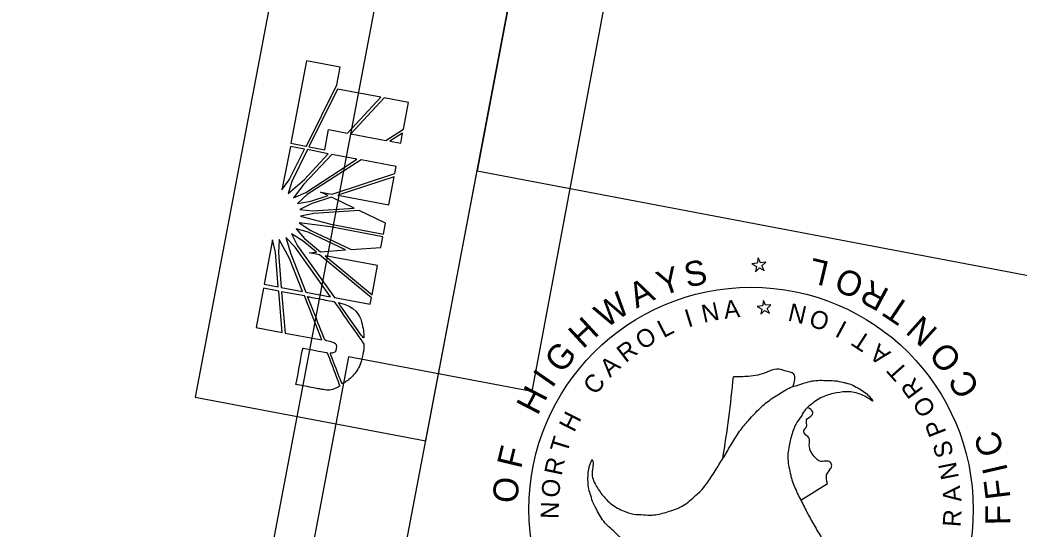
# Model space of a CAD drawing. Extents: x 1615680 to 1617075, y 898420 to 901376.
# Drawn here: x 1616769.3 to 1616971.6, y 900660.3 to 900763.4 of the extents above; entities that cross this region are included whole.
import ezdxf

# ---------------------------------------------------------------- set-up
doc = ezdxf.new("R2010")
doc.units = 0
for name, color, linetype in [('Default', 7, 'Continuous'), ('DEV BORDER CELL', 7, 'Continuous'), ('DEV DOT SWIRL SEAL CELL', 7, 'Continuous'), ('Scratch_Level_0', 7, 'Continuous'), ('Sheet Clip Boundary CELL', 7, 'Continuous'), ('Sheet Plan CELL', 7, 'Continuous'), ('Text', 7, 'Continuous')]:
    doc.layers.add(name, color=color, linetype=linetype)

msp = doc.modelspace()

# ---------------------------------------------------------------- linework, layer by layer
at = {"layer": 'Default'}
for p, q in [((1616827.31, 900755.17), (1616824.15, 900738.45)), ((1616834.16, 900753.88), (1616827.31, 900755.17)), ((1616833.49, 900750.32), (1616834.16, 900753.88)), ((1616827.31, 900737.85), (1616833.49, 900750.32)), ((1616833.63, 900749.42), (1616827.78, 900737.76)), ((1616842.41, 900747.76), (1616833.63, 900749.42)), ((1616835.63, 900740.51), (1616842.41, 900747.76)), ((1616843.03, 900747.65), (1616836.29, 900740.38)), ((1616847.97, 900746.71), (1616843.03, 900747.65)), ((1616846.95, 900741.32), (1616847.97, 900746.71)), ((1616831.04, 900737.15), (1616831.81, 900741.23)), ((1616831.81, 900741.23), (1616835.63, 900740.51)), ((1616836.29, 900740.38), (1616843.4, 900739.04)), ((1616843.4, 900739.04), (1616846.95, 900741.32)), ((1616846.8, 900740.53), (1616844.18, 900738.89)), ((1616846.41, 900738.47), (1616846.8, 900740.53)), ((1616824.07, 900737.82), (1616822.36, 900729.01)), ((1616826.93, 900737.28), (1616824.07, 900737.82)), ((1616824.15, 900738.45), (1616827.22, 900737.87)), ((1616827.22, 900737.87), (1616827.31, 900737.85)), ((1616827.78, 900737.76), (1616827.84, 900737.75)), ((1616827.84, 900737.75), (1616831.04, 900737.15)), ((1616844.18, 900738.89), (1616846.41, 900738.47)), ((1616823.84, 900731.04), (1616826.93, 900737.28)), ((1616827.54, 900737.17), (1616824.37, 900730.71)), ((1616832.45, 900736.19), (1616826.81, 900730.17)), ((1616826.95, 900731.13), (1616831.74, 900736.32)), ((1616831.74, 900736.32), (1616827.54, 900737.17)), ((1616837.54, 900735.22), (1616832.45, 900736.19)), ((1616827.18, 900728.51), (1616837.54, 900735.22)), ((1616838.37, 900735.07), (1616827.5, 900728.08)), ((1616845.51, 900733.72), (1616838.37, 900735.07)), ((1616845.25, 900732.31), (1616845.51, 900733.72)), ((1616832.52, 900728.14), (1616845.25, 900732.31)), ((1616845.08, 900731.66), (1616833.66, 900727.92)), ((1616844.01, 900725.97), (1616845.08, 900731.66)), ((1616822.36, 900729.01), (1616823.84, 900731.04)), ((1616823.59, 900728.31), (1616826.95, 900731.13)), ((1616824.37, 900730.71), (1616823.59, 900728.31)), ((1616826.81, 900730.17), (1616824.69, 900727.39)), ((1616824.69, 900727.39), (1616827.18, 900728.51)), ((1616827.5, 900728.08), (1616825.48, 900726.27)), ((1616828.21, 900726.76), (1616831.69, 900727.87)), ((1616832.4, 900727.52), (1616828.28, 900726.16)), ((1616831.69, 900727.87), (1616830.19, 900728.58)), ((1616830.19, 900728.58), (1616832.52, 900728.14)), ((1616836.99, 900725.33), (1616832.4, 900727.52)), ((1616833.66, 900727.92), (1616844.01, 900725.97)), ((1616825.48, 900726.27), (1616828.21, 900726.76)), ((1616828.28, 900726.16), (1616825.97, 900725.01)), ((1616828.57, 900724.79), (1616836.99, 900725.33)), ((1616825.97, 900725.01), (1616828.57, 900724.79)), ((1616828.83, 900724.24), (1616826.09, 900723.67)), ((1616826.09, 900723.67), (1616832.28, 900722.08)), ((1616837.99, 900724.87), (1616828.83, 900724.24)), ((1616843.31, 900722.28), (1616837.99, 900724.87)), ((1616832.18, 900721.51), (1616825.84, 900722.36)), ((1616825.84, 900722.36), (1616828.18, 900720.79)), ((1616842.79, 900719.51), (1616832.18, 900721.51)), ((1616832.28, 900722.08), (1616842.89, 900720.07)), ((1616842.89, 900720.07), (1616843.31, 900722.28)), ((1616825.04, 900717.42), (1616823.18, 900719.36)), ((1616823.18, 900719.36), (1616824.14, 900716.04)), ((1616824.31, 900720.1), (1616825.54, 900717.68)), ((1616826.67, 900718.65), (1616824.31, 900720.1)), ((1616825.24, 900721.11), (1616826.96, 900719.15)), ((1616827.65, 900720.42), (1616825.24, 900721.11)), ((1616826.96, 900719.15), (1616830.18, 900716.49)), ((1616835.2, 900716.86), (1616827.65, 900720.42)), ((1616828.18, 900720.79), (1616836.35, 900716.92)), ((1616842.37, 900717.33), (1616842.79, 900719.51)), ((1616820.45, 900718.87), (1616818.76, 900709.92)), ((1616821.03, 900716.4), (1616820.45, 900718.87)), ((1616821.82, 900718.94), (1616821.64, 900716.28)), ((1616823.88, 900715.14), (1616821.82, 900718.94)), ((1616832.19, 900707.38), (1616825.04, 900717.42)), ((1616825.54, 900717.68), (1616833.03, 900707.22)), ((1616829.39, 900716.41), (1616826.67, 900718.65)), ((1616836.35, 900716.92), (1616842.37, 900717.33)), ((1616821.61, 900709.38), (1616821.03, 900716.4)), ((1616821.64, 900716.28), (1616822.22, 900709.27)), ((1616826.53, 900708.45), (1616823.88, 900715.14)), ((1616824.14, 900716.04), (1616827.22, 900708.32)), ((1616827.87, 900716.29), (1616829.39, 900716.41)), ((1616829.97, 900715.89), (1616827.87, 900716.29)), ((1616840.5, 900707.17), (1616829.97, 900715.89)), ((1616830.18, 900716.49), (1616835.2, 900716.86)), ((1616841.73, 900713.72), (1616831.12, 900715.68)), ((1616831.12, 900715.68), (1616840.61, 900707.79)), ((1616840.61, 900707.79), (1616841.73, 900713.72)), ((1616818.64, 900709.09), (1616817.14, 900701.13)), ((1616821.71, 900708.51), (1616818.64, 900709.09)), ((1616818.76, 900709.92), (1616821.61, 900709.38)), ((1616822.22, 900709.27), (1616826.53, 900708.45)), ((1616822.41, 900700.13), (1616821.71, 900708.51)), ((1616826.9, 900707.53), (1616822.29, 900708.4)), ((1616822.29, 900708.4), (1616823.02, 900700.02)), ((1616830.44, 900698.62), (1616826.9, 900707.53)), ((1616827.22, 900708.32), (1616832.19, 900707.38)), ((1616833.03, 900707.22), (1616840.25, 900705.86)), ((1616840.25, 900705.86), (1616840.5, 900707.17)), ((1616817.14, 900701.13), (1616822.41, 900700.13)), ((1616823.02, 900700.02), (1616830.44, 900698.62))]:
    msp.add_line(p, q, dxfattribs=at)
for points in [[(1616827.78, 900737.76), (1616827.84, 900737.75), (1616831.04, 900737.15), (1616831.81, 900741.23), (1616835.63, 900740.51), (1616842.41, 900747.76), (1616833.63, 900749.42), (1616827.78, 900737.76)], [(1616836.29, 900740.38), (1616843.4, 900739.04), (1616846.95, 900741.32), (1616847.97, 900746.71), (1616843.03, 900747.65), (1616836.29, 900740.38), (1616836.29, 900740.38)], [(1616846.41, 900738.47), (1616846.41, 900738.47), (1616846.8, 900740.53), (1616844.18, 900738.89), (1616846.41, 900738.47)], [(1616823.84, 900731.04), (1616826.93, 900737.28), (1616824.07, 900737.82), (1616822.36, 900729.01), (1616823.84, 900731.04)], [(1616823.59, 900728.31), (1616826.95, 900731.13), (1616831.74, 900736.32), (1616827.54, 900737.17), (1616824.37, 900730.71), (1616823.59, 900728.31)], [(1616824.69, 900727.39), (1616827.18, 900728.51), (1616837.54, 900735.22), (1616832.45, 900736.19), (1616826.81, 900730.17), (1616824.69, 900727.39)], [(1616825.48, 900726.27), (1616828.21, 900726.76), (1616831.69, 900727.87), (1616830.19, 900728.58), (1616832.52, 900728.14), (1616845.25, 900732.31), (1616845.51, 900733.72), (1616838.37, 900735.07), (1616827.5, 900728.08), (1616825.48, 900726.27)], [(1616844.01, 900725.97), (1616845.08, 900731.66), (1616833.66, 900727.92), (1616844.01, 900725.97)], [(1616825.97, 900725.01), (1616828.57, 900724.79), (1616836.99, 900725.33), (1616832.4, 900727.52), (1616828.28, 900726.16), (1616825.97, 900725.01)], [(1616826.09, 900723.67), (1616832.28, 900722.08), (1616842.89, 900720.07), (1616843.31, 900722.28), (1616837.99, 900724.87), (1616828.83, 900724.24), (1616826.09, 900723.67)], [(1616828.18, 900720.79), (1616836.35, 900716.92), (1616842.37, 900717.33), (1616842.79, 900719.51), (1616832.18, 900721.51), (1616825.84, 900722.36), (1616828.18, 900720.79)], [(1616827.22, 900708.32), (1616832.19, 900707.38), (1616825.04, 900717.42), (1616823.18, 900719.36), (1616824.14, 900716.04), (1616827.22, 900708.32)], [(1616824.31, 900720.1), (1616825.54, 900717.68), (1616833.03, 900707.22), (1616840.25, 900705.86), (1616840.5, 900707.17), (1616829.97, 900715.89), (1616827.87, 900716.29), (1616829.39, 900716.41), (1616826.67, 900718.65), (1616824.31, 900720.1)], [(1616825.24, 900721.11), (1616826.96, 900719.15), (1616830.18, 900716.49), (1616835.2, 900716.86), (1616827.65, 900720.42), (1616825.24, 900721.11)], [(1616821.03, 900716.4), (1616820.45, 900718.87), (1616818.76, 900709.92), (1616821.61, 900709.38), (1616821.03, 900716.4)], [(1616822.22, 900709.27), (1616826.53, 900708.45), (1616823.88, 900715.14), (1616821.82, 900718.94), (1616821.64, 900716.28), (1616822.22, 900709.27)], [(1616840.61, 900707.79), (1616841.73, 900713.72), (1616831.12, 900715.68), (1616840.61, 900707.79)], [(1616822.41, 900700.13), (1616821.71, 900708.51), (1616818.64, 900709.09), (1616817.14, 900701.13), (1616822.41, 900700.13)], [(1616830.44, 900698.62), (1616826.9, 900707.53), (1616822.29, 900708.4), (1616823.02, 900700.02), (1616830.44, 900698.62)]]:
    msp.add_lwpolyline(points, dxfattribs=at)
for points in [[(1616833.44, 900696.87), (1616833.35, 900696.4), (1616833.01, 900696.04), (1616832.1, 900696.03), (1616832.1, 900696.03), (1616834.55, 900689.66), (1616834.55, 900689.66), (1616836.73, 900691.07), (1616838.37, 900693.67), (1616838.81, 900696.04), (1616838.93, 900696.66), (1616838.97, 900697.14), (1616838.96, 900697.82), (1616838.96, 900697.82), (1616832.91, 900706.39), (1616832.91, 900706.39), (1616832.91, 900706.39), (1616827.55, 900707.4), (1616827.55, 900707.4), (1616827.55, 900707.4), (1616831.11, 900698.49), (1616831.11, 900698.49), (1616833.11, 900698.11), (1616833.56, 900697.52), (1616833.44, 900696.87)], [(1616833.44, 900696.87), (1616833.35, 900696.4), (1616833.01, 900696.04), (1616832.1, 900696.03), (1616832.1, 900696.03), (1616834.55, 900689.66), (1616834.55, 900689.66), (1616836.73, 900691.07), (1616838.37, 900693.67), (1616838.81, 900696.04), (1616838.93, 900696.66), (1616838.97, 900697.14), (1616838.96, 900697.82), (1616838.96, 900697.82), (1616832.91, 900706.39), (1616832.91, 900706.39), (1616832.91, 900706.39), (1616827.55, 900707.4), (1616827.55, 900707.4), (1616827.55, 900707.4), (1616831.11, 900698.49), (1616831.11, 900698.49), (1616833.11, 900698.11), (1616833.56, 900697.52), (1616833.44, 900696.87)], [(1616833.75, 900706.23), (1616833.75, 900706.23), (1616838.97, 900698.83), (1616838.97, 900698.83), (1616838.8, 900702), (1616837.36, 900705.4), (1616833.75, 900706.23)], [(1616833.75, 900706.23), (1616833.75, 900706.23), (1616838.97, 900698.83), (1616838.97, 900698.83), (1616838.8, 900702), (1616837.36, 900705.4), (1616833.75, 900706.23)], [(1616826.59, 900696.98), (1616826.59, 900696.98), (1616825.2, 900689.61), (1616825.2, 900689.61), (1616825.2, 900689.61), (1616829.81, 900688.74), (1616829.81, 900688.74), (1616829.81, 900688.74), (1616830.29, 900688.65), (1616830.29, 900688.65), (1616831.74, 900688.38), (1616832.97, 900688.64), (1616834.09, 900689.29), (1616834.09, 900689.29), (1616831.55, 900696.04), (1616831.46, 900696.06), (1616831.46, 900696.06), (1616826.59, 900696.98), (1616826.59, 900696.98)], [(1616826.59, 900696.98), (1616826.59, 900696.98), (1616825.2, 900689.61), (1616825.2, 900689.61), (1616825.2, 900689.61), (1616829.81, 900688.74), (1616829.81, 900688.74), (1616829.81, 900688.74), (1616830.29, 900688.65), (1616830.29, 900688.65), (1616831.74, 900688.38), (1616832.97, 900688.64), (1616834.09, 900689.29), (1616834.09, 900689.29), (1616831.55, 900696.04), (1616831.46, 900696.06), (1616831.46, 900696.06), (1616826.59, 900696.98), (1616826.59, 900696.98)]]:
    msp.add_open_spline(points, degree=3, dxfattribs=at)
at = {"layer": 'DEV BORDER CELL'}
for points in [[(1616905.88, 900964.73), (1616861.86, 900732.87), (1616996.95, 900707.23), (1617040.97, 900939.08)], [(1616840.59, 900620.87), (1616861.86, 900732.87), (1616996.95, 900707.23), (1616975.68, 900595.22)]]:
    msp.add_lwpolyline(points, close=True, dxfattribs=at)
at = {"layer": 'DEV DOT SWIRL SEAL CELL'}
for p, q in [((1616918.77, 900715.25), (1616918.56, 900714.19)), ((1616919.23, 900714.26), (1616918.77, 900715.25)), ((1616918.56, 900714.19), (1616917.51, 900714.02)), ((1616917.51, 900714.02), (1616918.44, 900713.51)), ((1616918.44, 900713.51), (1616918.23, 900712.45)), ((1616918.23, 900712.45), (1616919.03, 900713.2)), ((1616919.03, 900713.2), (1616920, 900712.69)), ((1616920.32, 900714.39), (1616919.23, 900714.26)), ((1616919.52, 900713.63), (1616920.32, 900714.39)), ((1616920, 900712.69), (1616919.52, 900713.63)), ((1616919.62, 900705.56), (1616918.56, 900705.39)), ((1616918.56, 900705.39), (1616919.49, 900704.89)), ((1616919.82, 900706.62), (1616919.62, 900705.56)), ((1616920.28, 900705.64), (1616919.82, 900706.62)), ((1616921.37, 900705.76), (1616920.28, 900705.64)), ((1616920.58, 900705.01), (1616921.37, 900705.76)), ((1616921.05, 900704.06), (1616920.58, 900705.01)), ((1616919.49, 900704.89), (1616919.29, 900703.83)), ((1616919.29, 900703.83), (1616920.08, 900704.57)), ((1616920.08, 900704.57), (1616921.05, 900704.06)), ((1616927.43, 900666.17), (1616932.82, 900669.53))]:
    msp.add_line(p, q, dxfattribs=at)
msp.add_arc((1616681.63, 900713.24), 233.19, 350.4529, 354.5729, dxfattribs=at)
for points in [[(1616925.85, 900689.2), (1616926.01, 900691.68), (1616924.16, 900692.4), (1616922.56, 900692.74), (1616920.51, 900692.09), (1616916.81, 900691.24), (1616913.77, 900691.18)], [(1616885.09, 900674.44), (1616885.15, 900674.35), (1616885.14, 900671.73), (1616885.9, 900669.21), (1616887.35, 900667.1), (1616889.36, 900665.16), (1616892, 900663.79), (1616894.06, 900663.26), (1616895.09, 900663.25), (1616896.88, 900663.16), (1616898.33, 900663.29), (1616901.12, 900664.05), (1616903.92, 900665.29), (1616906.42, 900667.39), (1616906.62, 900667.57), (1616908.56, 900669.82), (1616910.25, 900672.43), (1616911.82, 900674.91), (1616913.38, 900677.54), (1616915.02, 900680.12), (1616916.87, 900682.4), (1616919.19, 900684.83), (1616921.43, 900686.67), (1616924.06, 900688.3), (1616925.37, 900689.03), (1616926.65, 900689.42), (1616929.69, 900690.32), (1616932.83, 900690.43), (1616934.72, 900690.32), (1616936.29, 900689.97), (1616936.55, 900689.92), (1616939.3, 900688.71), (1616941.48, 900686.96), (1616942.02, 900686.2)], [(1616942.02, 900686.2), (1616939.76, 900687.51), (1616937.22, 900688.12), (1616934.64, 900687.9), (1616931.95, 900687.13), (1616929.47, 900685.55), (1616927.98, 900684.03), (1616927.45, 900683.12), (1616926.46, 900681.67), (1616925.87, 900680.28), (1616925.1, 900677.53), (1616924.79, 900674.45), (1616925.36, 900671.25), (1616925.42, 900670.99), (1616926.44, 900668.18), (1616927.8, 900665.43), (1616929.16, 900662.79), (1616930.68, 900660.13), (1616932.13, 900657.42), (1616933.14, 900654.69), (1616934.09, 900651.45), (1616934.55, 900648.6), (1616934.65, 900645.52), (1616934.64, 900643.99), (1616934.34, 900642.71), (1616933.59, 900639.66), (1616932.13, 900636.85), (1616931.1, 900635.29), (1616929.97, 900634.12), (1616929.8, 900633.9), (1616927.41, 900632.12), (1616924.81, 900631.11), (1616923.83, 900630.99)], [(1616932.82, 900669.53), (1616932.64, 900671.29), (1616933.43, 900672.58), (1616933.66, 900673.23), (1616933.35, 900673.86), (1616931.24, 900674.09), (1616930.36, 900674.75), (1616929.12, 900677.31), (1616929.08, 900678.76), (1616927.99, 900680.03), (1616928.1, 900680.44), (1616928.58, 900681.01), (1616928.57, 900682.48), (1616929.71, 900683.44), (1616929.78, 900684.12), (1616928.83, 900684.85)], [(1616923.83, 900630.99), (1616926.14, 900632.33), (1616927.91, 900634.21), (1616929.01, 900636.54), (1616929.7, 900639.28), (1616929.57, 900642.22), (1616928.98, 900644.28), (1616928.5, 900645.19), (1616927.68, 900646.76), (1616926.81, 900647.94), (1616924.8, 900650.02), (1616922.29, 900651.8), (1616919.26, 900652.93), (1616919, 900653), (1616916.04, 900653.54), (1616912.98, 900653.71), (1616910.03, 900653.83), (1616906.95, 900653.87), (1616903.91, 900653.96), (1616901.02, 900654.45), (1616897.76, 900655.26), (1616895.03, 900656.27), (1616892.3, 900657.74), (1616891.02, 900658.51), (1616890.04, 900659.4), (1616887.76, 900661.61), (1616886.08, 900664.25), (1616885.25, 900665.94), (1616884.78, 900667.48), (1616884.69, 900667.74), (1616884.32, 900670.71), (1616884.74, 900673.47), (1616885.15, 900674.35)]]:
    msp.add_spline(points, degree=3, dxfattribs=at)
at = {"layer": 'Scratch_Level_0'}
msp.add_lwpolyline([(1616054.34, 901080.76), (1615793.19, 899705.33), (1616726.52, 899528.12), (1616890.46, 900391.55), (1616774.26, 900413.61), (1616871.48, 900925.61)], close=True, dxfattribs=at)
at = {"layer": 'Sheet Clip Boundary CELL'}
msp.add_lwpolyline([(1616176.29, 901060.7), (1616913.78, 900900.04), (1616896.28, 900812.91), (1616872.94, 900688.21), (1616835.87, 900695.21), (1616753.94, 900262.18), (1616898.09, 900233.43), (1616663.91, 899565.73), (1616252.62, 899604.04), (1615894.68, 899796.73), (1615981.58, 900932.46), (1616145.94, 900899.57)], close=True, dxfattribs=at)
at = {"layer": 'Sheet Plan CELL'}
msp.add_lwpolyline([(1616859.19, 900973.59), (1616804.79, 900687.04), (1616851.47, 900678.18), (1616905.88, 900964.73)], close=True, dxfattribs=at)
at = {"layer": 'Text'}
msp.add_circle((1616917.34, 900664.32), 44.97, dxfattribs=at)

# ---------------------------------------------------------------- texts
at = {"layer": 'DEV DOT SWIRL SEAL CELL'}
for s, height, rotation, p in [('Y', 5.04, 18.9977, (1616899.33, 900707.45)), ('S', 5.04, 12.4743, (1616904.4, 900709.18)), ('A', 5.04, 26.0256, (1616894.13, 900704.96)), ('W', 5.04, 35.0626, (1616887.96, 900700.86)), ('N', 3.63, 12.1007, (1616907.73, 900702.07)), ('A', 3.63, 7.0227, (1616912.01, 900702.88)), ('N', 3.63, 166.9823, (1616928.85, 900705.33)), ('H', 5.04, 42.7126, (1616883.29, 900696.66)), ('I', 3.63, 17.1788, (1616904.59, 900701.12)), ('O', 3.63, 162.1763, (1616933.52, 900703.81)), ('L', 3.63, 27.335, (1616899.6, 900698.96)), ('I', 3.63, 152.0201, (1616937.01, 900702.05)), ('O', 3.63, 32.4131, (1616895.39, 900696.49)), ('T', 3.63, 146.942, (1616941.93, 900699.08)), ('G', 5.04, 50.7661, (1616879.02, 900691.62)), ('R', 3.63, 37.4912, (1616891.93, 900693.88)), ('A', 3.63, 141.8639, (1616945.78, 900696.08)), ('A', 3.63, 42.5693, (1616888.77, 900690.92)), ('T', 3.63, 131.7077, (1616949.3, 900692.41)), ('I', 5.04, 55.0534, (1616877.05, 900688.7)), ('C', 3.63, 52.7254, (1616885.92, 900687.29)), ('R', 3.63, 126.6297, (1616952.37, 900688.51)), ('H', 5.04, 62.7034, (1616874.1, 900683.16)), ('O', 3.63, 121.5516, (1616954.91, 900684.44)), ('H', 3.63, 62.8816, (1616881.51, 900679.75)), ('P', 3.63, 111.3954, (1616956.93, 900679.91)), ('F', 5.04, 76.5069, (1616870.74, 900672.37)), ('S', 3.63, 106.3173, (1616958.42, 900675.42)), ('R', 3.63, 78.1158, (1616878.97, 900670.99)), ('N', 3.63, 101.2392, (1616959.44, 900670.73)), ('O', 5.04, 85.0143, (1616869.99, 900665.43)), ('O', 3.63, 83.1939, (1616878.41, 900666.54)), ('A', 3.63, 96.1611, (1616959.95, 900665.98)), ('N', 3.63, 88.272, (1616878.34, 900662.34)), ('R', 3.63, 86.005, (1616959.73, 900660.67))]:
    msp.add_text(s, height=height, rotation=rotation, dxfattribs=at).set_placement(p)
at = {"layer": 'Text'}
for s, height, rotation, p in [('L', 5.04, 166.6784, (1616933.41, 900714.4)), ('O', 5.04, 158.239, (1616940.59, 900711.5)), ('R', 5.04, 152.0012, (1616945.58, 900708.69)), ('T', 5.04, 146.1304, (1616949.97, 900705.57)), ('N', 5.04, 138.1413, (1616955.38, 900700.64)), ('O', 5.04, 129.702, (1616960.3, 900694.66)), ('C', 5.04, 122.3301, (1616963.84, 900688.9)), ('T', 3.63, 73.0378, (1616880.06, 900675.5)), ('C', 5.04, 107.2527, (1616968.63, 900675.95)), ('I', 5.04, 102.9996, (1616969.35, 900672.12)), ('F', 5.04, 97.012, (1616969.88, 900666.65)), ('F', 5.04, 91.0244, (1616969.84, 900661.16))]:
    msp.add_text(s, height=height, rotation=rotation, dxfattribs=at).set_placement(p)

doc.saveas('drawing.dxf')
